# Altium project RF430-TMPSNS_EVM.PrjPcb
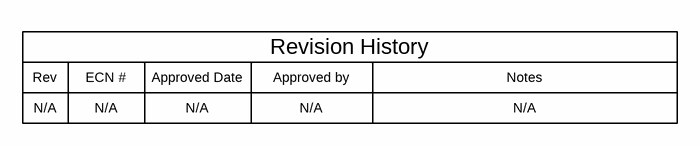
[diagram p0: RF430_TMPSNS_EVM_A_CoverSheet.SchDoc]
TID: N/A; TechSupport: http://www.ti.com/support; SCH_Rev: A; PRJ_Title: RF430-TMPSNS-EVM; PRJ_Number: RF430-TMPSNS-EVM; PRJ_Engineer: Eddie LaCost; PRJ_Customer: Public Release; PCB_Rev: A; PCB_Layout: Eddie LaCost; CopyrightYear: 2016
3 sheets, 42 parts. Net scope: global (net labels, ports and power ports of the same name join across sheets).
Board file: RF430_TMPSNS_EVM_A.PcbDoc
Sheets:
  RF430_TMPSNS_EVM_A_CoverSheet.SchDoc
  RF430_TMPSNS_EVM_A.SchDoc
  RF430_TMPSNS_EVM_A_Hardware.SchDoc

## Sheet RF430_TMPSNS_EVM_A_CoverSheet.SchDoc
size 431 x 279 mm; Date: Not shown in title block; ApprovedBy: Not shown in title block; CheckedBy: Not shown in title block; Author: Not shown in title block; CompanyName: Not shown in title block; Engineer: Not shown in title block; Organization: Not shown in title block; Address1: Not shown in title block; Address2: Not shown in title block; Address3: Not shown in title block; Address4: Not shown in title block; DocumentNumber: 1; Revision: Use project parameter SCH_Rev; SheetNumber: 1; SheetTotal: 3; PageSetup: Record=PageOptions¦CenterHorizontal=True¦CenterVertical=True¦PrintScale=1.00¦XCorrection=1.00¦YCorrection=1.00¦PrintKind=0¦BorderSize=5000000¦LeftOffset=0¦BottomOffset=0¦Orientation=2¦PaperLength=1000¦PaperWidth=1000¦Scale=100¦PaperSource=15¦PrintQuality=600¦MediaType=1¦DitherType=10¦PaperKind=Letter¦PrintScaleMode=1

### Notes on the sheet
- Rev
- N/A
- ECN #
- Approved Date
- Approved by
- Revision History
- Notes

## Sheet RF430_TMPSNS_EVM_A.SchDoc
size 431 x 279 mm; Date: Not shown in title block; ApprovedBy: Not shown in title block; CheckedBy: Not shown in title block; Author: Not shown in title block; CompanyName: Not shown in title block; Engineer: Not shown in title block; Organization: Not shown in title block; Address1: Not shown in title block; Address2: Not shown in title block; Address3: Not shown in title block; Address4: Not shown in title block; DocumentNumber: 1; Revision: Use project parameter SCH_Rev; SheetNumber: 2; SheetTotal: 3; PageSetup: Record=PageOptions¦CenterHorizontal=True¦CenterVertical=True¦PrintScale=1.00¦XCorrection=1.00¦YCorrection=1.00¦PrintKind=0¦BorderSize=5000000¦LeftOffset=0¦BottomOffset=0¦Orientation=2¦PaperLength=1000¦PaperWidth=1000¦Scale=100¦PaperSource=15¦PrintQuality=600¦MediaType=1¦DitherType=10¦PaperKind=Letter¦PrintScaleMode=1
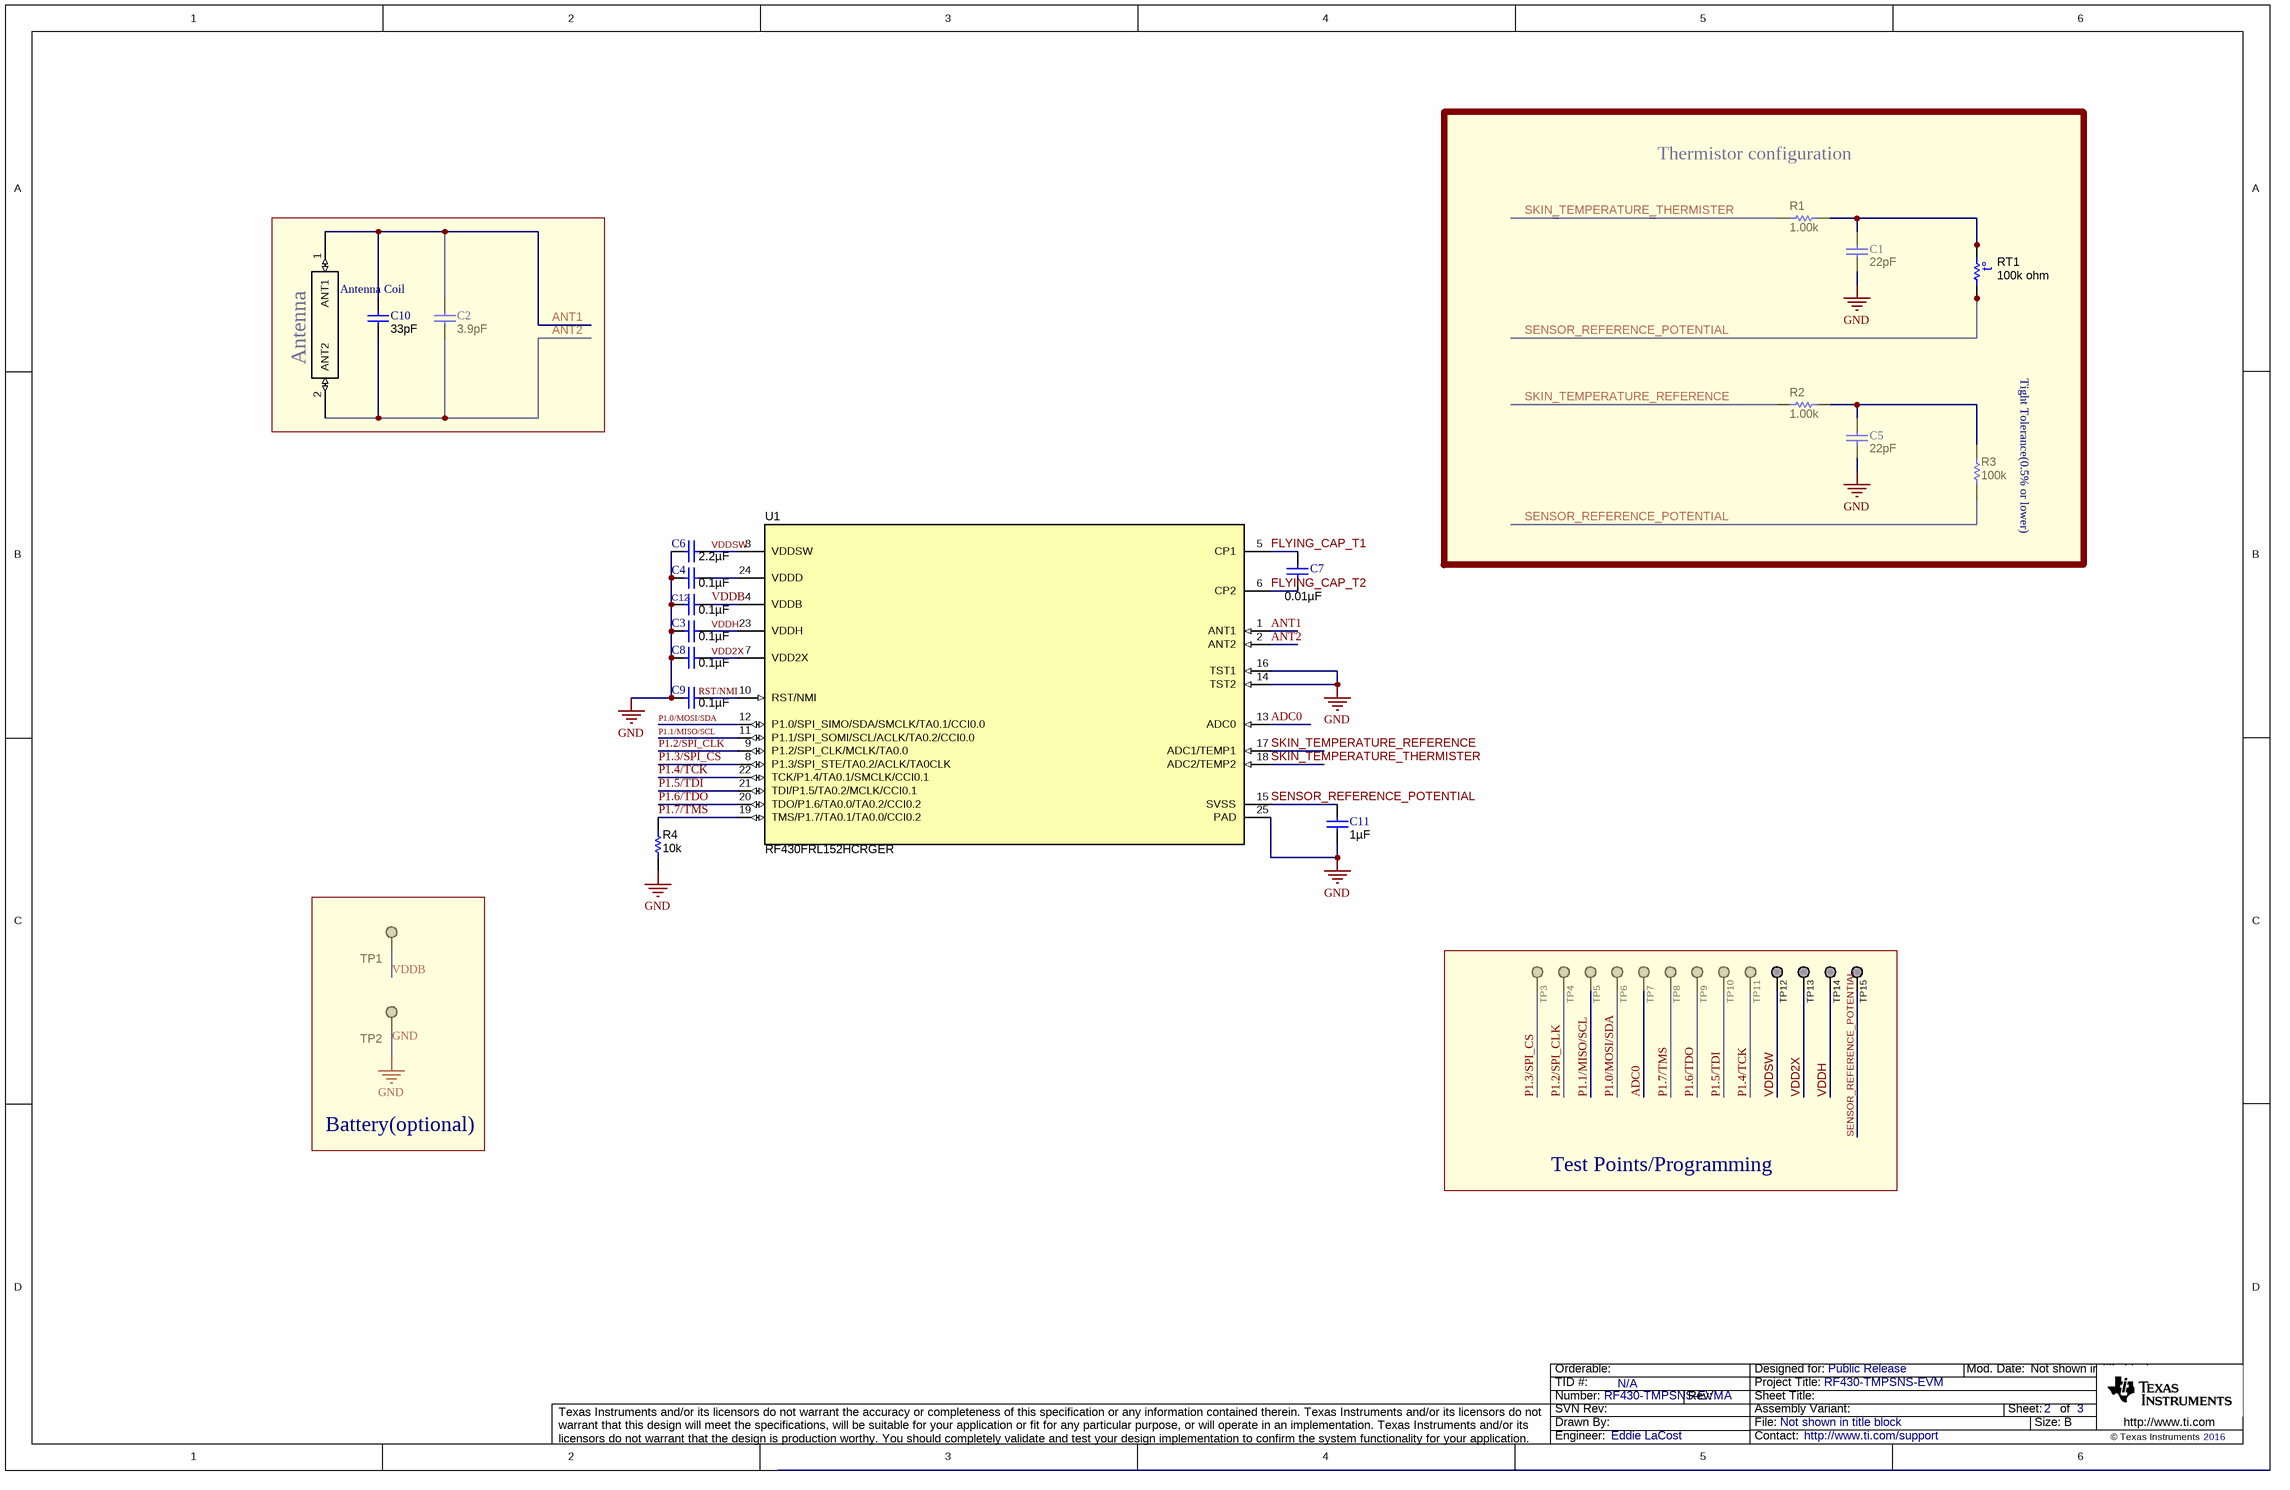
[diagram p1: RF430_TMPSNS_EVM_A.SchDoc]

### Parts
Antenna_Coil  Antenna Coil  [PCBComponent_1]
C1  ValueDisplayed: 22pF  [0402]  (hidden comment: C1005C0G1H220J050BA)
C2  ValueDisplayed: 3.9pF  [0402]  (hidden comment: GRM1555C1E3R9CA01D)
C3  ValueDisplayed: 0.1µF  [0402]  (hidden comment: 885012205037)
C4  ValueDisplayed: 0.1µF  [0402]  (hidden comment: 885012205037)
C5  ValueDisplayed: 22pF  [0402]  (hidden comment: C1005C0G1H220J050BA)
C6  ValueDisplayed: 2.2µF  [0402]  (hidden comment: C1005X5R1A225K050BC)
C7  ValueDisplayed: 0.01µF  [0402]  (hidden comment: 885012205031)
C8  ValueDisplayed: 0.1µF  [0402]  (hidden comment: 885012205037)
C9  ValueDisplayed: 0.1µF  [0402]  (hidden comment: 885012205037)
C10  ValueDisplayed: 33pF  [0402]  (hidden comment: GRM1555C1E330JA01D)
C11  ValueDisplayed: 1µF  [0402]  (hidden comment: C1005X7S1A105K050BC)
C12  ValueDisplayed: 0.1µF  [0402]  (hidden comment: 885012205037)
R1  ValueDisplayed: 1.00k  [0402]  (hidden comment: CRCW04021K00FKED)
R2  ValueDisplayed: 1.00k  [0402]  (hidden comment: CRCW04021K00FKED)
R3  ValueDisplayed: 100k  [0402]  (hidden comment: CRCW0402100KJNED)
R4  ValueDisplayed: 10k  [0402]  (hidden comment: CRCW040210K0JNED)
RT1  value 100k ohm  [0603]  (hidden comment: ERT-J1VS104FA)
TP1  TESTPOINT  [TESTPOINT]  (value not drawn)  (no BOM)
TP2  TESTPOINT  [TESTPOINT]  (value not drawn)  (no BOM)
TP3  TESTPOINT  [TESTPOINT]  (value not drawn)  (no BOM)
TP4  TESTPOINT  [TESTPOINT]  (value not drawn)  (no BOM)
TP5  TESTPOINT  [TESTPOINT]  (value not drawn)  (no BOM)
TP6  TESTPOINT  [TESTPOINT]  (value not drawn)  (no BOM)
TP7  TESTPOINT  [TESTPOINT]  (value not drawn)  (no BOM)
TP8  TESTPOINT  [TESTPOINT]  (value not drawn)  (no BOM)
TP9  TESTPOINT  [TESTPOINT]  (value not drawn)  (no BOM)
TP10  TESTPOINT  [TESTPOINT]  (value not drawn)  (no BOM)
TP11  TESTPOINT  [TESTPOINT]  (value not drawn)  (no BOM)
TP12  TESTPOINT  [TESTPOINT]  (value not drawn)  (no BOM)
TP13  TESTPOINT  [TESTPOINT]  (value not drawn)  (no BOM)
TP14  TESTPOINT  [TESTPOINT]  (value not drawn)  (no BOM)
TP15  TESTPOINT  [TESTPOINT]  (value not drawn)  (no BOM)
U1  RF430FRL152HCRGER  [RGE0024C]

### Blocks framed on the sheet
Thermistor configuration: C1 C5 R1-R3 RT1
Antenna: Antenna_Coil C2 C10
Battery(optional): TP1 TP2
Test Points/Programming: TP3-TP15

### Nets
GND: C1.2 C3.1 C4.1 C5.2 C6.1 C8.1 C9.1 C11.1 C12.2 R4.1 TP2.1 U1.14(TST2) U1.16(TST1) U1.25(PAD)
ADC0: TP7.1 U1.13(ADC0)
ANT1: Antenna_Coil.1(ANT1) C2.1 C10.1 U1.1(ANT1)
ANT2: Antenna_Coil.2(ANT2) C2.2 C10.2 U1.2(ANT2)
FLYING_CAP_T1: C7.1 U1.5(CP1)
FLYING_CAP_T2: C7.2 U1.6(CP2)
P1.0/MOSI/SDA: TP6.1 U1.12(P1.0/SPI_SIMO/SDA/SMCLK/TA0.1/CCI0.0)
P1.1/MISO/SCL: TP5.1 U1.11(P1.1/SPI_SOMI/SCL/ACLK/TA0.2/CCI0.0)
P1.2/SPI_CLK: TP4.1 U1.9(P1.2/SPI_CLK/MCLK/TA0.0)
P1.3/SPI_CS: TP3.1 U1.8(P1.3/SPI_STE/TA0.2/ACLK/TA0CLK)
P1.4/TCK: TP11.1 U1.22(TCK/P1.4/TA0.1/SMCLK/CCI0.1)
P1.5/TDI: TP10.1 U1.21(TDI/P1.5/TA0.2/MCLK/CCI0.1)
P1.6/TDO: TP9.1 U1.20(TDO/P1.6/TA0.0/TA0.2/CCI0.2)
P1.7/TMS: R4.2 TP8.1 U1.19(TMS/P1.7/TA0.1/TA0.0/CCI0.2)
SENSOR_REFERENCE_POTENTIAL: C11.2 R3.1 RT1.1 TP15.1 U1.15(SVSS)
SKIN_TEMPERATURE_REFERENCE: R2.1 U1.17(ADC1/TEMP1)
SKIN_TEMPERATURE_THERMISTER: R1.1 U1.18(ADC2/TEMP2)
VDD2X: C8.2 TP13.1 U1.7(VDD2X)
VDDB: C12.1 TP1.1 U1.4(VDDB)
VDDH: C3.2 TP14.1 U1.23(VDDH)
VDDSW: C6.2 TP12.1 U1.3(VDDSW)
NetC1_1: C1.1 R1.2 RT1.2
NetC4_2: C4.2 U1.24(VDDD)
NetC5_1: C5.1 R2.2 R3.2
NetC9_2: C9.2 U1.10(RST/NMI)

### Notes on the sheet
- (near R3) Tight Tolerance(0.5% or lower)
- Labels drawn without touching a wire or pin: RST/NMI

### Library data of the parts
Antenna_Coil = Component_1
C1 C5 = C1005C0G1H220J050BA: CAP, CERM, 22 pF, 50 V, +/- 5%, C0G/NP0, 0402; Manufacturer: TDK; Value: 22pF; Polarized: N; CompType: Capacitor; U/M: EA; Cap_F: 0.000000000022; Tolerance_%: 5; Value1: Unknown; VDC_V: 50; Value2: 50V; TaMin_C: -55; TaMax_C: 125; AEC Category: Q200
C2 = GRM1555C1E3R9CA01D: CAP, CERM, 3.9 pF, 25 V, +/- 5%, C0G/NP0, 0402; Manufacturer: MuRata; Value: 3.9pF; Polarized: N; CompType: Capacitor; U/M: EA; Cap_F: 0.0000000000039; Tolerance_%: 5; Value1: Unknown; VDC_V: 25; Value2: 25V; TaMin_C: -55; TaMax_C: 125; AEC Category: Q200
C3 C4 C8 C9 = 885012205037: CAP, CERM, 0.1 µF, 16 V, +/- 10%, X7R, 0402; Manufacturer: Wurth Elektronik; Value: 0.1uF; Polarized: N; CompType: Capacitor; U/M: EA; Cap_F: 0.0000001; Tolerance_%: 10; Value1: Unknown; VDC_V: 16; Value2: 16V; TaMin_C: -55; TaMax_C: 125; AEC Category: Q200
C6 = C1005X5R1A225K050BC: CAP, CERM, 2.2 µF, 10 V, +/- 10%, X5R, 0402; Manufacturer: TDK; Value: 2.2uF; Polarized: N; CompType: Capacitor; U/M: EA; Cap_F: 0.0000022; Tolerance_%: 10; Value1: Unknown; Value2: 10V; TaMin_C: -55; TaMax_C: 85; AEC Category: Q200
C7 = 885012205031: CAP, CERM, 0.01 µF, 16 V, +/- 10%, X7R, 0402; Manufacturer: Wurth Elektronik; Value: 0.01uF; Polarized: N; CompType: Capacitor; U/M: EA; Cap_F: 0.00000001; Tolerance_%: 10; Value1: Unknown; VDC_V: 16; Value2: 16V; TaMin_C: -55; TaMax_C: 125; AEC Category: Q200
C10 = GRM1555C1E330JA01D: CAP, CERM, 33 pF, 25 V, +/- 5%, C0G/NP0, 0402; Manufacturer: MuRata; Value: 33pF; Polarized: N; CompType: Capacitor; U/M: EA; Cap_F: 0.000000000033; Tolerance_%: 5; Value1: Unknown; VDC_V: 25; Value2: 25V; TaMin_C: -55; TaMax_C: 125; AEC Category: Q200
C11 = C1005X7S1A105K050BC: CAP, CERM, 1 µF, 10 V, +/- 10%, X7S, 0402; Manufacturer: TDK; Value: 1uF; Polarized: N; CompType: Capacitor; U/M: EA; Cap_F: 0.000001; Tolerance_%: 10; Value1: Unknown; Value2: 10V; TaMin_C: -55; TaMax_C: 125; AEC Category: Q200
C12 = 885012205037: CAP, CERM, 0.1 µF, 16 V, +/- 10%, X7R, 0402; Manufacturer: Wurth Elektronik; Polarized: N; CompType: Capacitor; Value: 0.1uF; U/M: EA; Cap_F: 0.0000001; Tolerance_%: 10; Value1: Unknown; VDC_V: 16; Value2: 16V; TaMin_C: -55; TaMax_C: 125; AEC Category: Q200
R1 R2 = CRCW04021K00FKED: RES, 1.00 k, 1%, 0.063 W, 0402; Manufacturer: Vishay-Dale; CompType: Resistor; Res_ohm: 1000; Value: 1.00k; Value_Code: 1k00; Tolerance_%: 1; Power_W: 0.063; Value2: 0.063W; VDC_V: 50; TempCo: 100 ppm/C; EIA_Code: E96; U/M: EA
R3 = CRCW0402100KJNED: RES, 100 k, 5%, 0.063 W, 0402; Manufacturer: Vishay-Dale; CompType: Resistor; Res_ohm: 100000; Value: 100k; Tolerance_%: 5; Power_W: 0.063; Value2: 0.063W; VDC_V: 50; TempCo: 200 ppm/C; EIA_Code: E24; U/M: EA
R4 = CRCW040210K0JNED: RES, 10 k, 5%, 0.063 W, 0402; Manufacturer: Vishay-Dale; CompType: Resistor; Res_ohm: 10000; Value: 10k; Value_Code: 10k0; Tolerance_%: 5; Power_W: 0.063; Value2: 0.063W; VDC_V: 50; TempCo: 200 ppm/C; EIA_Code: E24; U/M: EA
RT1 = ERT-J1VS104FA: Thermistor NTC, 100k ohm, 1%, 0603; Manufacturer: Panasonic; Tolerance_%: 1; Power_W: 0.1; TaMin_C: -40; TaMax_C: 125; U/M: EA
TP1-TP15 = TESTPOINT: TEST POINT.  No entry in BOM.
U1 = RF430FRL152HCRGER: NFC ISO 15693 Sensor Transponder, RGE0024C; Manufacturer: Texas Instruments; SymbolCreator: Altium; CompType: IC; U/M: EA

## Sheet RF430_TMPSNS_EVM_A_Hardware.SchDoc
size 431 x 279 mm; Date: Not shown in title block; ApprovedBy: Not shown in title block; CheckedBy: Not shown in title block; Author: Not shown in title block; CompanyName: Not shown in title block; Engineer: Not shown in title block; Organization: Not shown in title block; Address1: Not shown in title block; Address2: Not shown in title block; Address3: Not shown in title block; Address4: Not shown in title block; DocumentNumber: 1; Revision: Use project parameter SCH_Rev; SheetNumber: 3; SheetTotal: 3; PageSetup: Record=PageOptions¦CenterHorizontal=True¦CenterVertical=True¦PrintScale=1.00¦XCorrection=1.00¦YCorrection=1.00¦PrintKind=0¦BorderSize=5000000¦LeftOffset=0¦BottomOffset=0¦Orientation=2¦PaperLength=1000¦PaperWidth=1000¦Scale=100¦PaperSource=15¦PrintQuality=600¦MediaType=1¦DitherType=10¦PaperKind=Letter¦PrintScaleMode=1
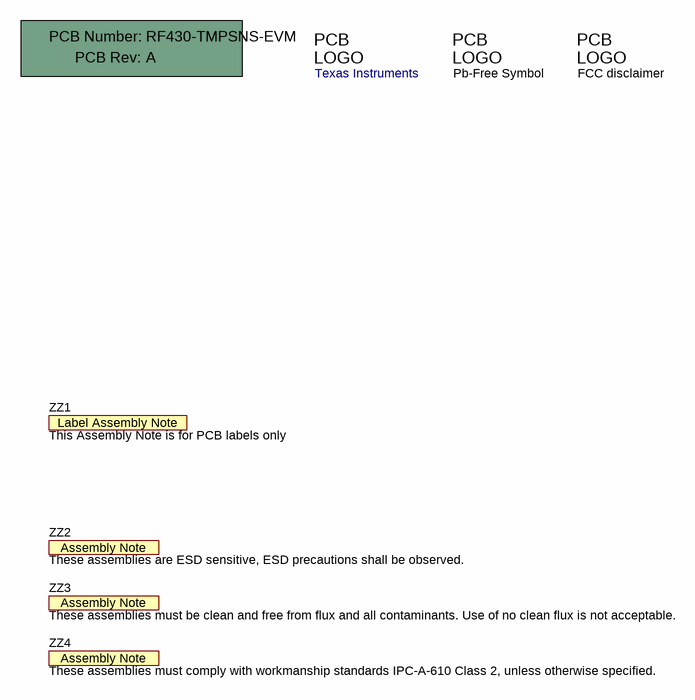
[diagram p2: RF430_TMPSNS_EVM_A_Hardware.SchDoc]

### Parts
!PCB  Printed Circuit Board  (value not drawn)  (mechanical)
Logo2  Pb-Free Symbol  [Pb-Free_Overlay_Small]  (no BOM)
Logo3  FCC disclaimer  [FCC_disclaimer]  (no BOM)
Logo?  Texas Instruments  [TI_Symbol_Overlay_Small]  (no BOM)
ZZ1  This Assembly Note is for PCB labels only  [AssemblyNoteLabel]  (no BOM)
ZZ2  These assemblies are ESD sensitive, ESD precautions shall be observed.  [AssemblyNote]  (no BOM)
ZZ3  These assemblies must be clean and free from flux and all contaminants. Use of no clean flux is not acceptable.  [AssemblyNote]  (no BOM)
ZZ4  These assemblies must comply with workmanship standards IPC-A-610 Class 2, unless otherwise specified.  [AssemblyNote]  (no BOM)

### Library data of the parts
!PCB = PCB: Manufacturer: Any; PartNumber: RF430-TMPSNS-EVM; SymbolCreator: a0412235
Logo2 = Pb-Free: SymbolCreator: a0412235
Logo3 = FCC_disclaimer: SymbolCreator: codlsc
Logo? = TI_Logo: Texas Instrument Corporate Signature; SymbolCreator: a0412235
ZZ1 = AssemblyNoteLabel: SymbolCreator: a0412235
ZZ2-ZZ4 = AssemblyNote: SymbolCreator: codlsc

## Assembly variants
001: not fitted Antenna Coil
